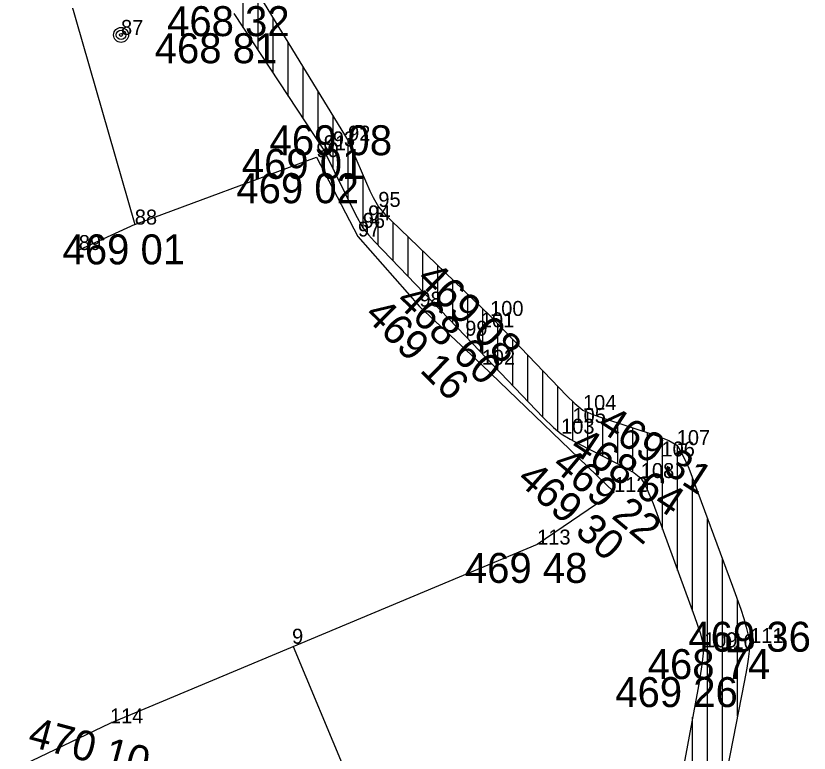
# Model space of a CAD drawing. Extents: x -559180 to -551373, y -1076947 to -1072071.
# Drawn here: x -553700.91 to -553674.43, y -1075778.44 to -1075753.83 of the extents above; entities that cross this region are included whole.
import ezdxf

# ---------------------------------------------------------------- set-up
doc = ezdxf.new("R2010")
doc.units = 0
for name, color, linetype in [('12_PLOTY', 7, 'Continuous'), ('1_VODA_ZN', 7, 'Continuous'), ('20_EL_ZN', 7, 'Continuous'), ('28_VODA', 7, 'Continuous'), ('32', 7, 'Continuous'), ('3_BODY', 7, 'Continuous'), ('6_VYSKY', 7, 'Continuous')]:
    doc.layers.add(name, color=color, linetype=linetype)

# ---------------------------------------------------------------- blocks, each defined once
blk = doc.blocks.new('SLDP')
at = {"layer": '20_EL_ZN'}
for radius in [0.25, 0.158, 0.05]:
    blk.add_circle((0, 0), radius, dxfattribs=at)
blk = doc.blocks.new('POINT_DISPLAY')
blk.add_line((0, 0), (0, 0))

msp = doc.modelspace()

# ---------------------------------------------------------------- linework, layer by layer
at = {"layer": '12_PLOTY'}
for p, q in [((-553700.042, -1075750), (-553696.94, -1075760.8)), ((-553700.042, -1075750), (-553696.94, -1075760.8)), ((-553696.94, -1075760.8), (-553690.88, -1075758.55)), ((-553696.94, -1075760.8), (-553690.88, -1075758.55)), ((-553690.88, -1075758.55), (-553689.49, -1075761.2)), ((-553690.88, -1075758.55), (-553689.49, -1075761.2)), ((-553696.94, -1075760.8), (-553698.81, -1075761.65)), ((-553696.94, -1075760.8), (-553698.81, -1075761.65)), ((-553689.49, -1075761.2), (-553687.44, -1075763.54)), ((-553689.49, -1075761.2), (-553687.44, -1075763.54)), ((-553687.44, -1075763.54), (-553685.36, -1075765.48)), ((-553687.44, -1075763.54), (-553685.36, -1075765.48)), ((-553685.36, -1075765.48), (-553680.94, -1075769.73)), ((-553685.36, -1075765.48), (-553680.94, -1075769.73)), ((-553680.94, -1075769.73), (-553683.51, -1075771.48)), ((-553680.94, -1075769.73), (-553683.51, -1075771.48)), ((-553683.51, -1075771.48), (-553697.77, -1075777.45)), ((-553683.51, -1075771.48), (-553697.77, -1075777.45)), ((-553691.649, -1075774.888), (-553686.24, -1075787.81)), ((-553697.77, -1075777.45), (-553700.91, -1075778.95)), ((-553697.77, -1075777.45), (-553700.91, -1075778.95))]:
    msp.add_line(p, q, dxfattribs=at)
at = {"layer": '28_VODA'}
for p, q in [((-553692.87, -1075753), (-553689.82, -1075758)), ((-553692.87, -1075753), (-553689.82, -1075758)), ((-553693.63, -1075753.76), (-553690.63, -1075758.32)), ((-553693.63, -1075753.76), (-553690.63, -1075758.32))]:
    msp.add_line(p, q, dxfattribs=at)
for points in [[(-553689.82, -1075758), (-553689.091, -1075759.669), (-553688.982, -1075759.895), (-553688.81, -1075760.21)], [(-553689.82, -1075758), (-553689.091, -1075759.669), (-553688.982, -1075759.895), (-553688.81, -1075760.21)], [(-553690.63, -1075758.32), (-553689.585, -1075760.442), (-553689.33, -1075760.91)], [(-553690.63, -1075758.32), (-553689.585, -1075760.442), (-553689.33, -1075760.91)], [(-553688.81, -1075760.21), (-553688.596, -1075760.455), (-553688.375, -1075760.67), (-553685.08, -1075763.85)], [(-553688.81, -1075760.21), (-553688.596, -1075760.455), (-553688.375, -1075760.67), (-553685.08, -1075763.85)], [(-553689.33, -1075760.91), (-553689.137, -1075761.141), (-553688.939, -1075761.362), (-553685.91, -1075764.51)], [(-553689.33, -1075760.91), (-553689.137, -1075761.141), (-553688.939, -1075761.362), (-553685.91, -1075764.51)], [(-553685.08, -1075763.85), (-553682.524, -1075766.509), (-553682.251, -1075766.775), (-553681.98, -1075766.99)], [(-553685.08, -1075763.85), (-553682.524, -1075766.509), (-553682.251, -1075766.775), (-553681.98, -1075766.99)], [(-553685.91, -1075764.51), (-553683.309, -1075767.244), (-553682.967, -1075767.568), (-553682.71, -1075767.78)], [(-553685.91, -1075764.51), (-553683.309, -1075767.244), (-553682.967, -1075767.568), (-553682.71, -1075767.78)], [(-553681.98, -1075766.99), (-553681.649, -1075767.136), (-553681.396, -1075767.231), (-553679.464, -1075767.864), (-553679.253, -1075767.947), (-553679.113, -1075768.012), (-553678.85, -1075768.16)], [(-553681.98, -1075766.99), (-553681.649, -1075767.136), (-553681.396, -1075767.231), (-553679.464, -1075767.864), (-553679.253, -1075767.947), (-553679.113, -1075768.012), (-553678.85, -1075768.16)], [(-553682.71, -1075767.78), (-553682.409, -1075767.967), (-553682.093, -1075768.132), (-553680.579, -1075768.904), (-553680.272, -1075769.09), (-553680.05, -1075769.26)], [(-553682.71, -1075767.78), (-553682.409, -1075767.967), (-553682.093, -1075768.132), (-553680.579, -1075768.904), (-553680.272, -1075769.09), (-553680.05, -1075769.26)], [(-553678.85, -1075768.16), (-553678.746, -1075768.324), (-553678.644, -1075768.507), (-553678.45, -1075768.929), (-553676.987, -1075772.866), (-553676.712, -1075773.637), (-553676.614, -1075773.944), (-553676.531, -1075774.242), (-553676.4, -1075774.77)], [(-553678.85, -1075768.16), (-553678.746, -1075768.324), (-553678.644, -1075768.507), (-553678.45, -1075768.929), (-553676.987, -1075772.866), (-553676.712, -1075773.637), (-553676.614, -1075773.944), (-553676.531, -1075774.242), (-553676.4, -1075774.77)], [(-553680.05, -1075769.26), (-553679.939, -1075769.446), (-553679.848, -1075769.623), (-553679.641, -1075770.108), (-553678.257, -1075773.878), (-553678.071, -1075774.426), (-553677.94, -1075774.91)], [(-553680.05, -1075769.26), (-553679.939, -1075769.446), (-553679.848, -1075769.623), (-553679.641, -1075770.108), (-553678.257, -1075773.878), (-553678.071, -1075774.426), (-553677.94, -1075774.91)], [(-553676.4, -1075774.77), (-553676.462, -1075775.307), (-553676.506, -1075775.611), (-553676.598, -1075776.071), (-553677.346, -1075779.892), (-553677.405, -1075780.2), (-553677.489, -1075780.573), (-553677.538, -1075780.792), (-553677.61, -1075781.06)], [(-553676.4, -1075774.77), (-553676.462, -1075775.307), (-553676.506, -1075775.611), (-553676.598, -1075776.071), (-553677.346, -1075779.892), (-553677.405, -1075780.2), (-553677.489, -1075780.573), (-553677.538, -1075780.792), (-553677.61, -1075781.06)], [(-553677.94, -1075774.91), (-553677.995, -1075775.408), (-553678.093, -1075776.02), (-553678.638, -1075778.954), (-553678.711, -1075779.35), (-553678.82, -1075779.83)], [(-553677.94, -1075774.91), (-553677.995, -1075775.408), (-553678.093, -1075776.02), (-553678.638, -1075778.954), (-553678.711, -1075779.35), (-553678.82, -1075779.83)]]:
    msp.add_lwpolyline(points, dxfattribs=at)
at = {"layer": '32'}
for p, q in [((-553693.32, -1075754.231), (-553693.32, -1075752.393)), ((-553693.32, -1075754.231), (-553693.32, -1075752.393)), ((-553692.82, -1075754.991), (-553692.82, -1075753.082)), ((-553692.82, -1075754.991), (-553692.82, -1075753.082)), ((-553692.32, -1075755.751), (-553692.32, -1075753.902)), ((-553692.32, -1075755.751), (-553692.32, -1075753.902)), ((-553691.82, -1075756.511), (-553691.82, -1075754.721)), ((-553691.82, -1075756.511), (-553691.82, -1075754.721)), ((-553691.32, -1075757.271), (-553691.32, -1075755.541)), ((-553691.32, -1075757.271), (-553691.32, -1075755.541)), ((-553690.82, -1075758.031), (-553690.82, -1075756.361)), ((-553690.82, -1075758.031), (-553690.82, -1075756.361)), ((-553690.32, -1075758.949), (-553690.32, -1075757.18)), ((-553690.32, -1075758.949), (-553690.32, -1075757.18)), ((-553689.82, -1075759.965), (-553689.82, -1075758)), ((-553689.82, -1075759.965), (-553689.82, -1075758)), ((-553689.32, -1075760.922), (-553689.32, -1075759.145)), ((-553689.32, -1075760.922), (-553689.32, -1075759.145)), ((-553688.82, -1075761.486), (-553688.82, -1075760.192)), ((-553688.82, -1075761.486), (-553688.82, -1075760.192)), ((-553688.32, -1075762.005), (-553688.32, -1075760.723)), ((-553688.32, -1075762.005), (-553688.32, -1075760.723)), ((-553687.82, -1075762.525), (-553687.82, -1075761.206)), ((-553687.82, -1075762.525), (-553687.82, -1075761.206)), ((-553687.32, -1075763.045), (-553687.32, -1075761.688)), ((-553687.32, -1075763.045), (-553687.32, -1075761.688)), ((-553686.82, -1075763.564), (-553686.82, -1075762.171)), ((-553686.82, -1075763.564), (-553686.82, -1075762.171)), ((-553686.32, -1075764.084), (-553686.32, -1075762.653)), ((-553686.32, -1075764.084), (-553686.32, -1075762.653)), ((-553685.82, -1075764.605), (-553685.82, -1075763.136)), ((-553685.82, -1075764.605), (-553685.82, -1075763.136)), ((-553685.32, -1075765.13), (-553685.32, -1075763.618)), ((-553685.32, -1075765.13), (-553685.32, -1075763.618)), ((-553684.82, -1075765.656), (-553684.82, -1075764.12)), ((-553684.82, -1075765.656), (-553684.82, -1075764.12)), ((-553684.32, -1075766.181), (-553684.32, -1075764.641)), ((-553684.32, -1075766.181), (-553684.32, -1075764.641)), ((-553683.82, -1075766.707), (-553683.82, -1075765.161)), ((-553683.82, -1075766.707), (-553683.82, -1075765.161)), ((-553683.32, -1075767.232), (-553683.32, -1075765.681)), ((-553683.32, -1075767.232), (-553683.32, -1075765.681)), ((-553682.82, -1075767.689), (-553682.82, -1075766.201)), ((-553682.82, -1075767.689), (-553682.82, -1075766.201)), ((-553682.32, -1075768.013), (-553682.32, -1075766.708)), ((-553682.32, -1075768.013), (-553682.32, -1075766.708)), ((-553681.82, -1075768.271), (-553681.82, -1075767.061)), ((-553681.82, -1075768.271), (-553681.82, -1075767.061)), ((-553681.32, -1075768.526), (-553681.32, -1075767.256)), ((-553681.32, -1075768.526), (-553681.32, -1075767.256)), ((-553680.82, -1075768.781), (-553680.82, -1075767.42)), ((-553680.82, -1075768.781), (-553680.82, -1075767.42)), ((-553680.32, -1075769.061), (-553680.32, -1075767.584)), ((-553680.32, -1075769.061), (-553680.32, -1075767.584)), ((-553679.82, -1075769.689), (-553679.82, -1075767.747)), ((-553679.82, -1075769.689), (-553679.82, -1075767.747)), ((-553679.32, -1075770.982), (-553679.32, -1075767.925)), ((-553679.32, -1075770.982), (-553679.32, -1075767.925)), ((-553678.82, -1075772.344), (-553678.82, -1075768.207)), ((-553678.82, -1075772.344), (-553678.82, -1075768.207)), ((-553678.32, -1075773.706), (-553678.32, -1075769.279)), ((-553678.32, -1075773.706), (-553678.32, -1075769.279)), ((-553677.82, -1075781.502), (-553677.82, -1075770.624)), ((-553677.82, -1075781.502), (-553677.82, -1075770.624)), ((-553677.32, -1075779.759), (-553677.32, -1075771.97)), ((-553677.32, -1075779.759), (-553677.32, -1075771.97)), ((-553676.82, -1075777.205), (-553676.82, -1075773.334)), ((-553676.82, -1075777.205), (-553676.82, -1075773.334)), ((-553678.32, -1075782.435), (-553678.32, -1075777.242)), ((-553678.32, -1075782.435), (-553678.32, -1075777.242))]:
    msp.add_line(p, q, dxfattribs=at)

# ---------------------------------------------------------------- block references
at = {"layer": '1_VODA_ZN'}
for p in [(-553697.4, -1075754.47), (-553689.82, -1075758), (-553690.63, -1075758.32), (-553690.33, -1075758.19), (-553690.88, -1075758.55), (-553688.81, -1075760.21), (-553689.15, -1075760.66), (-553696.94, -1075760.8), (-553689.33, -1075760.91), (-553689.49, -1075761.2), (-553698.81, -1075761.65), (-553687.44, -1075763.54), (-553685.08, -1075763.85), (-553685.39, -1075764.23), (-553685.91, -1075764.51), (-553685.36, -1075765.48), (-553681.98, -1075766.99), (-553682.33, -1075767.42), (-553682.71, -1075767.78), (-553678.85, -1075768.16), (-553679.36, -1075768.54), (-553680.05, -1075769.26), (-553680.94, -1075769.73), (-553683.51, -1075771.48), (-553691.69, -1075774.79), (-553676.4, -1075774.77), (-553677.94, -1075774.91), (-553677.36, -1075774.97), (-553697.77, -1075777.45)]:
    msp.add_blockref('POINT_DISPLAY', p, dxfattribs=at)
at = {"layer": '20_EL_ZN'}
msp.add_blockref('SLDP', (-553697.4, -1075754.47), dxfattribs=at)
msp.add_blockref('SLDP', (-553697.4, -1075754.47), dxfattribs=at)

# ---------------------------------------------------------------- texts
at = {"layer": '3_BODY'}
for s, p in [('87', (-553697.4, -1075754.47)), ('92', (-553689.82, -1075758)), ('91', (-553690.63, -1075758.32)), ('93', (-553690.33, -1075758.19)), ('90', (-553690.88, -1075758.55)), ('95', (-553688.81, -1075760.21)), ('94', (-553689.15, -1075760.66)), ('88', (-553696.94, -1075760.8)), ('96', (-553689.33, -1075760.91)), ('97', (-553689.49, -1075761.2)), ('89', (-553698.81, -1075761.65)), ('98', (-553687.44, -1075763.54)), ('100', (-553685.08, -1075763.85)), ('101', (-553685.39, -1075764.23)), ('99', (-553685.91, -1075764.51)), ('102', (-553685.36, -1075765.48)), ('104', (-553681.98, -1075766.99)), ('105', (-553682.33, -1075767.42)), ('103', (-553682.71, -1075767.78)), ('107', (-553678.85, -1075768.16)), ('106', (-553679.36, -1075768.54)), ('108', (-553680.05, -1075769.26)), ('112', (-553680.94, -1075769.73)), ('113', (-553683.51, -1075771.48)), ('111', (-553676.4, -1075774.77)), ('9', (-553691.69, -1075774.79)), ('109', (-553677.94, -1075774.91)), ('110', (-553677.36, -1075774.97)), ('114', (-553697.77, -1075777.45))]:
    msp.add_text(s, height=0.5, dxfattribs=at).set_placement(p)
at = {"layer": '6_VYSKY'}
for s, p in [('468 32', (-553695.862, -1075754.511)), ('468 81', (-553696.275, -1075755.415)), ('469 08', (-553692.442, -1075758.486)), ('469 01', (-553693.368, -1075759.274)), ('469 02', (-553693.549, -1075760.088)), ('469 01', (-553699.351, -1075762.128)), ('469 48', (-553685.922, -1075772.76)), ('469 36', (-553678.461, -1075775.057)), ('468 74', (-553679.818, -1075775.97)), ('469 26', (-553680.901, -1075776.904))]:
    msp.add_text(s, height=1, dxfattribs=at).set_placement(p)
for s, rotation, p in [('469 08', 316.0031, (-553687.571, -1075762.664)), ('468 60', 316.5724, (-553688.27, -1075763.408)), ('468 60', 316.5724, (-553688.27, -1075763.408)), ('468 60', 316.5724, (-553688.27, -1075763.408)), ('468 60', 316.5724, (-553688.27, -1075763.408)), ('469 16', 315.4002, (-553689.311, -1075763.863)), ('469 31', 327.0993, (-553681.539, -1075767.621)), ('468 64', 326.4849, (-553682.455, -1075768.333)), ('469 22', 320.1516, (-553683.06, -1075768.901)), ('469 30', 318.3468, (-553684.23, -1075769.362)), ('469 30', 318.3468, (-553684.23, -1075769.362)), ('469 30', 318.3468, (-553684.23, -1075769.362)), ('469 30', 318.3468, (-553684.23, -1075769.362)), ('470 10', 344.9765, (-553700.552, -1075778.188))]:
    msp.add_text(s, height=1, rotation=rotation, dxfattribs=at).set_placement(p)

doc.saveas('drawing.dxf')
